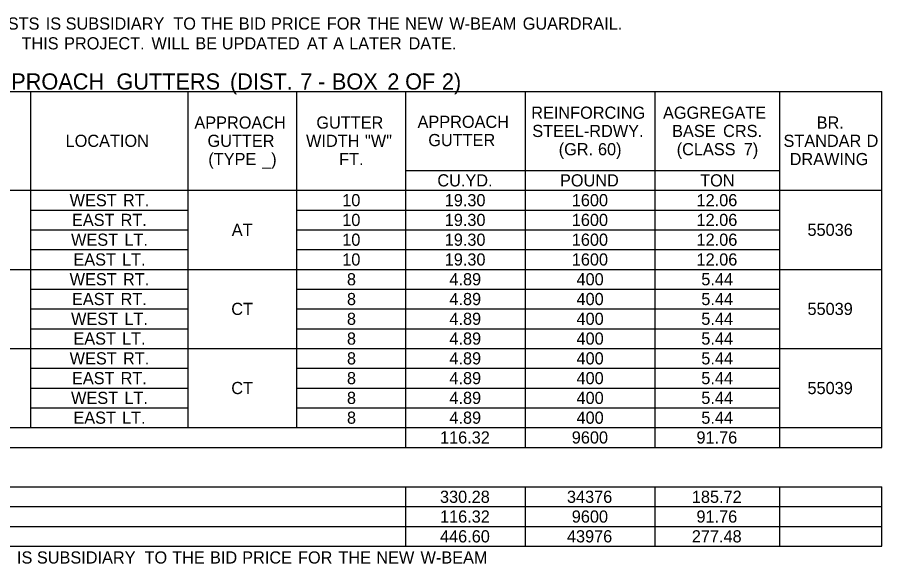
# Model space of a CAD drawing. Extents: x 544478 to 1930787, y -1948294 to 596640.
# Drawn here: x 559788.1 to 560214, y -1946735.6 to -1946466.2 of the extents above; entities that cross this region are included whole.
import ezdxf

# ---------------------------------------------------------------- set-up
doc = ezdxf.new("R2010")
doc.units = 0
doc.layers.add('Default', color=7, linetype='Continuous')

msp = doc.modelspace()

# ---------------------------------------------------------------- linework, layer by layer
at = {"layer": 'Default'}
for p, q in [((559563.64, -1946502.71), (560213.97, -1946502.71)), ((559794.72, -1946668.46), (559794.72, -1946502.71)), ((559872.23, -1946668.46), (559872.23, -1946502.71)), ((559925.85, -1946668.46), (559925.85, -1946502.71)), ((559979.48, -1946678.21), (559979.48, -1946502.71)), ((560038.47, -1946678.21), (560038.47, -1946502.71)), ((560102.33, -1946678.21), (560102.33, -1946502.71)), ((560163.75, -1946678.21), (560163.75, -1946502.71)), ((560213.97, -1946678.21), (560213.97, -1946502.71)), ((559979.48, -1946541.71), (560163.75, -1946541.71)), ((560038.47, -1946551.46), (560038.47, -1946541.71)), ((560102.33, -1946551.46), (560102.33, -1946541.71)), ((560163.75, -1946551.46), (560163.75, -1946541.71)), ((559563.64, -1946551.46), (560213.97, -1946551.46)), ((560163.75, -1946551.46), (560213.97, -1946551.46)), ((559794.72, -1946561.21), (559872.23, -1946561.21)), ((559794.72, -1946561.21), (559872.23, -1946561.21)), ((559925.85, -1946561.21), (560102.33, -1946561.21)), ((559925.85, -1946561.21), (560038.47, -1946561.21)), ((560038.47, -1946561.21), (560163.75, -1946561.21)), ((559794.72, -1946570.96), (559872.23, -1946570.96)), ((559794.72, -1946570.96), (559872.23, -1946570.96)), ((559925.85, -1946570.96), (560102.33, -1946570.96)), ((559925.85, -1946570.96), (560038.47, -1946570.96)), ((560038.47, -1946570.96), (560163.75, -1946570.96)), ((559794.72, -1946580.71), (559872.23, -1946580.71)), ((559794.72, -1946580.71), (559872.23, -1946580.71)), ((559925.85, -1946580.71), (560102.33, -1946580.71)), ((559925.85, -1946580.71), (560038.47, -1946580.71)), ((560038.47, -1946580.71), (560163.75, -1946580.71)), ((559563.64, -1946590.46), (560213.97, -1946590.46)), ((559794.72, -1946590.46), (559872.23, -1946590.46)), ((559872.23, -1946590.46), (559925.85, -1946590.46)), ((559925.85, -1946590.46), (560102.33, -1946590.46)), ((560102.33, -1946590.46), (560213.97, -1946590.46)), ((559794.72, -1946600.21), (559872.23, -1946600.21)), ((559794.72, -1946600.21), (559872.23, -1946600.21)), ((559925.85, -1946600.21), (560102.33, -1946600.21)), ((559925.85, -1946600.21), (560038.47, -1946600.21)), ((560038.47, -1946600.21), (560163.75, -1946600.21)), ((559794.72, -1946609.96), (559872.23, -1946609.96)), ((559794.72, -1946609.96), (559872.23, -1946609.96)), ((559925.85, -1946609.96), (560102.33, -1946609.96)), ((559925.85, -1946609.96), (560038.47, -1946609.96)), ((560038.47, -1946609.96), (560163.75, -1946609.96)), ((559794.72, -1946619.71), (559872.23, -1946619.71)), ((559794.72, -1946619.71), (559872.23, -1946619.71)), ((559925.85, -1946619.71), (560102.33, -1946619.71)), ((559925.85, -1946619.71), (560038.47, -1946619.71)), ((560038.47, -1946619.71), (560163.75, -1946619.71)), ((559563.64, -1946629.46), (560213.97, -1946629.46)), ((559794.72, -1946629.46), (559872.23, -1946629.46)), ((559872.23, -1946629.46), (559925.85, -1946629.46)), ((559925.85, -1946629.46), (560102.33, -1946629.46)), ((560102.33, -1946629.46), (560213.97, -1946629.46)), ((559794.72, -1946639.21), (559872.23, -1946639.21)), ((559794.72, -1946639.21), (559872.23, -1946639.21)), ((559925.85, -1946639.21), (560163.75, -1946639.21)), ((559794.72, -1946648.96), (559872.23, -1946648.96)), ((559794.72, -1946648.96), (559872.23, -1946648.96)), ((559925.85, -1946648.96), (559979.48, -1946648.96)), ((559925.85, -1946648.96), (560163.75, -1946648.96)), ((559794.72, -1946658.71), (559872.23, -1946658.71)), ((559794.72, -1946658.71), (559872.23, -1946658.71)), ((559925.85, -1946658.71), (559979.48, -1946658.71)), ((559925.85, -1946658.71), (560163.75, -1946658.71)), ((559563.64, -1946668.46), (560213.97, -1946668.46)), ((559794.72, -1946668.46), (559872.23, -1946668.46)), ((559872.23, -1946668.46), (559925.85, -1946668.46)), ((559925.85, -1946668.46), (559979.48, -1946668.46)), ((559979.48, -1946668.46), (560102.33, -1946668.46)), ((560102.33, -1946668.46), (560213.97, -1946668.46)), ((559563.64, -1946678.21), (560213.97, -1946678.21)), ((559563.64, -1946697.71), (560213.97, -1946697.71)), ((559563.64, -1946697.71), (560213.97, -1946697.71)), ((559979.48, -1946726.96), (559979.48, -1946697.71)), ((560038.47, -1946726.96), (560038.47, -1946697.71)), ((560038.47, -1946726.96), (560038.47, -1946697.71)), ((560102.33, -1946726.96), (560102.33, -1946697.71)), ((560163.75, -1946726.96), (560163.75, -1946697.71)), ((560213.97, -1946726.96), (560213.97, -1946697.71)), ((559563.64, -1946707.46), (560213.97, -1946707.46)), ((559563.64, -1946717.21), (560213.97, -1946717.21)), ((559979.48, -1946726.96), (559979.48, -1946717.21)), ((560102.33, -1946726.96), (560102.33, -1946717.21)), ((560163.75, -1946726.96), (560163.75, -1946717.21)), ((559563.64, -1946726.96), (560213.97, -1946726.96))]:
    msp.add_line(p, q, dxfattribs=at)

# ---------------------------------------------------------------- texts
for s, height, p in [(' POSTS', 6, (559769.59, -1946472.26)), (' IS', 6, (559799.9, -1946472.26)), (' SUBSIDIARY', 6, (559809.71, -1946472.26)), (' TO', 6, (559862.76, -1946472.26)), (' THE', 6, (559876.36, -1946472.26)), (' BID', 6, (559895.01, -1946472.26)), (' PRICE', 6, (559910.86, -1946472.26)), (' FOR', 6, (559938.36, -1946472.26)), (' THE', 6, (559958.28, -1946472.26)), (' NEW', 6, (559976.93, -1946472.26)), (' W-BEAM', 6, (559998.72, -1946472.26)), (' GUARDRAIL.', 6, (560034.88, -1946472.26)), (' THIS', 6, (559787.95, -1946482.01)), (' PROJECT.', 6, (559808.94, -1946482.01)), (' WILL', 6, (559852, -1946482.01)), (' BE', 6, (559873.59, -1946482.01)), (' UPDATED', 6, (559886.65, -1946482.01)), (' AT', 6, (559928.6, -1946482.01)), (' A', 6, (559941.47, -1946482.01)), (' LATER', 6, (559949.4, -1946482.01)), (' DATE.', 6, (559978.64, -1946482.01)), ('APPROACH', 8, (559770.85, -1946501.83)), (' GUTTERS', 8, (559833.96, -1946501.83)), (' (DIST.', 8, (559889.93, -1946501.83)), (' 7', 8, (559924.55, -1946501.83)), (' BOX', 8, (559940.12, -1946501.83)), (' 2', 8, (559967.44, -1946501.83)), (' OF', 8, (559976.2, -1946501.83)), (' 2)', 8, (559994.3, -1946501.83)), (' -', 8, (559933.38, -1946501.83)), ('REINFORCING', 6, (560041.31, -1946516.21)), ('AGGREGATE', 6, (560106.23, -1946516.21)), ('APPROACH', 6, (559875.37, -1946521.08)), ('GUTTER', 6, (559935.45, -1946521.08)), ('APPROACH', 6, (559985.31, -1946520.71)), ('BR.', 6, (560181.93, -1946521.08)), ('STEEL-RDWY.', 6, (560041.81, -1946525.21)), ('BASE', 6, (560110.71, -1946525.21)), (' CRS.', 6, (560133.59, -1946525.21)), ('LOCATION', 6, (559811.92, -1946530.08)), ('GUTTER', 6, (559881.83, -1946530.08)), ('WIDTH', 6, (559930.37, -1946530.08)), (' "W"', 6, (559957.19, -1946530.08)), ('GUTTER', 6, (559990.6, -1946529.71)), ('STANDAR', 6, (560165.57, -1946530.08)), ('D', 6, (560206.52, -1946530.08)), ('(GR.', 6, (560054.84, -1946534.21)), (' 60)', 6, (560071.96, -1946534.21)), ('(CLASS', 6, (560112.97, -1946534.21)), (' 7)', 6, (560143.77, -1946534.21)), ('(TYPE', 6, (559882.23, -1946539.08)), (' _)', 6, (559906.51, -1946539.08)), ('FT.', 6, (559946.67, -1946539.08)), ('DRAWING', 6, (560168.62, -1946539.08)), ('CU.YD.', 6, (559995.06, -1946549.58)), ('POUND', 6, (560055.47, -1946549.58)), ('TON', 6, (560124.53, -1946549.58)), ('WEST', 6, (559813.9, -1946559.33)), (' RT.', 6, (559837.95, -1946559.33)), ('10', 6, (559948.21, -1946559.33)), ('19.30', 6, (559998.69, -1946559.33)), ('1600', 6, (560061.28, -1946559.33)), ('12.06', 6, (560122.75, -1946559.33)), ('EAST', 6, (559815.06, -1946569.08)), (' RT.', 6, (559836.79, -1946569.08)), ('10', 6, (559948.21, -1946569.08)), ('19.30', 6, (559998.69, -1946569.08)), ('1600', 6, (560061.28, -1946569.08)), ('12.06', 6, (560122.75, -1946569.08)), ('AT', 6, (559893.77, -1946573.96)), ('55036', 6, (560177.4, -1946573.96)), ('WEST', 6, (559814.6, -1946578.83)), ('10', 6, (559948.21, -1946578.83)), ('19.30', 6, (559998.69, -1946578.83)), ('1600', 6, (560061.28, -1946578.83)), ('12.06', 6, (560122.75, -1946578.83)), (' LT.', 6, (559838.65, -1946578.83)), ('EAST', 6, (559815.75, -1946588.58)), (' LT.', 6, (559837.49, -1946588.58)), ('10', 6, (559948.21, -1946588.58)), ('19.30', 6, (559998.69, -1946588.58)), ('1600', 6, (560061.28, -1946588.58)), ('12.06', 6, (560122.75, -1946588.58)), ('WEST', 6, (559813.9, -1946598.33)), (' RT.', 6, (559837.95, -1946598.33)), ('8', 6, (559950.52, -1946598.33)), ('4.89', 6, (560001, -1946598.33)), ('400', 6, (560063.61, -1946598.33)), ('5.44', 6, (560125.09, -1946598.33)), ('EAST', 6, (559815.06, -1946608.08)), (' RT.', 6, (559836.79, -1946608.08)), ('8', 6, (559950.52, -1946608.08)), ('4.89', 6, (560001, -1946608.08)), ('400', 6, (560063.61, -1946608.08)), ('5.44', 6, (560125.09, -1946608.08)), ('CT', 6, (559893.54, -1946612.96)), ('55039', 6, (560177.4, -1946612.96)), ('WEST', 6, (559814.6, -1946617.83)), (' LT.', 6, (559838.65, -1946617.83)), ('8', 6, (559950.52, -1946617.83)), ('4.89', 6, (560001, -1946617.83)), ('400', 6, (560063.61, -1946617.83)), ('5.44', 6, (560125.09, -1946617.83)), ('EAST', 6, (559815.75, -1946627.58)), (' LT.', 6, (559837.49, -1946627.58)), ('8', 6, (559950.52, -1946627.58)), ('4.89', 6, (560001, -1946627.58)), ('400', 6, (560063.61, -1946627.58)), ('5.44', 6, (560125.09, -1946627.58)), ('WEST', 6, (559813.9, -1946637.33)), (' RT.', 6, (559837.95, -1946637.33)), ('8', 6, (559950.52, -1946637.33)), ('4.89', 6, (560001, -1946637.33)), ('400', 6, (560063.61, -1946637.33)), ('5.44', 6, (560125.09, -1946637.33)), ('EAST', 6, (559815.06, -1946647.08)), (' RT.', 6, (559836.79, -1946647.08)), ('8', 6, (559950.52, -1946647.08)), ('4.89', 6, (560001, -1946647.08)), ('400', 6, (560063.61, -1946647.08)), ('5.44', 6, (560125.09, -1946647.08)), ('CT', 6, (559893.54, -1946651.96)), ('55039', 6, (560177.4, -1946651.96)), ('WEST', 6, (559814.6, -1946656.83)), (' LT.', 6, (559838.65, -1946656.83)), ('8', 6, (559950.52, -1946656.83)), ('4.89', 6, (560001, -1946656.83)), ('400', 6, (560063.61, -1946656.83)), ('5.44', 6, (560125.09, -1946656.83)), ('EAST', 6, (559815.75, -1946666.58)), (' LT.', 6, (559837.49, -1946666.58)), ('8', 6, (559950.52, -1946666.58)), ('4.89', 6, (560001, -1946666.58)), ('400', 6, (560063.61, -1946666.58)), ('5.44', 6, (560125.09, -1946666.58)), ('116.32', 6, (559996.37, -1946676.33)), ('9600', 6, (560061.28, -1946676.33)), ('91.76', 6, (560122.71, -1946676.33)), ('330.28', 6, (559996.35, -1946705.58)), ('34376', 6, (560058.9, -1946705.58)), ('185.72', 6, (560120.44, -1946705.58)), ('116.32', 6, (559996.37, -1946715.33)), ('9600', 6, (560061.28, -1946715.33)), ('91.76', 6, (560122.71, -1946715.33)), ('446.60', 6, (559996.37, -1946725.08)), ('43976', 6, (560058.9, -1946725.08)), ('277.48', 6, (560120.42, -1946725.08)), (' IS', 6, (559785.73, -1946735.51)), (' SUBSIDIARY', 6, (559795.54, -1946735.51)), (' TO', 6, (559848.58, -1946735.51)), (' THE', 6, (559862.18, -1946735.51)), (' BID', 6, (559880.83, -1946735.51)), (' PRICE', 6, (559896.68, -1946735.51)), (' FOR', 6, (559924.19, -1946735.51)), (' THE', 6, (559944.1, -1946735.51)), (' NEW', 6, (559962.75, -1946735.51)), (' W-BEAM', 6, (559984.54, -1946735.51))]:
    msp.add_text(s, height=height, dxfattribs=at).set_placement(p)

doc.saveas('drawing.dxf')
